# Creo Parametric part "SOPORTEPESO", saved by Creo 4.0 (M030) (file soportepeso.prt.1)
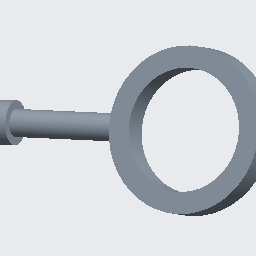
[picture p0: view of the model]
Units: millimeter Newton Second (mmNs); MM, TONNE, SECS

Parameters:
  MODELED_BY = "AJ"

Created from: MMNS_PART_SOLID.PRT

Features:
  1. datum plane "RIGHT"
  2. datum plane "TOP"
  3. datum plane "FRONT"
  4. coordinate system
  5. extrusion "Extrude 1"
  6. extrusion "Extrude 2"
  7. extrusion "Extrude 3"

Surfaces: 4 plane, 4 cylinder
